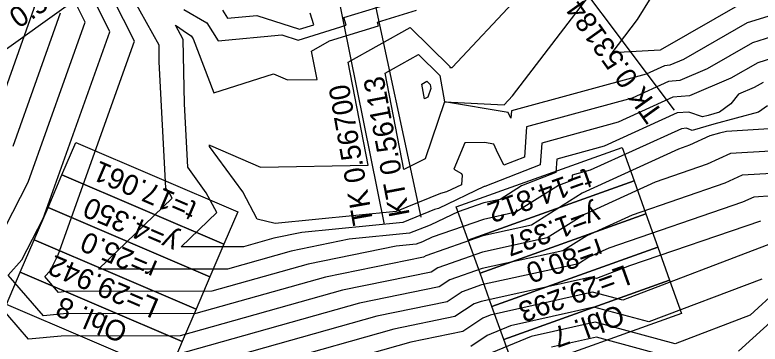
# Model space of a CAD drawing. Extents: x -549394 to -546608, y -1037055 to -1033629.
# Drawn here: x -548193 to -548066.1, y -1035675.8 to -1035619.7 of the extents above; entities that cross this region are included whole.
import ezdxf

# ---------------------------------------------------------------- set-up
doc = ezdxf.new("R2010")
doc.units = 0
for name, color, linetype in [('hlavni_vrst', 7, 'Continuous'), ('norm_vrst', 7, 'Continuous'), ('x_popis_oblouky_C11', 7, 'Continuous')]:
    doc.layers.add(name, color=color, linetype=linetype)

msp = doc.modelspace()

# ---------------------------------------------------------------- linework, layer by layer
at = {"layer": 'hlavni_vrst'}
for p, q in [((-548176.82, -1035622.58), (-548181.99, -1035612.19)), ((-548108.23, -1035633.5), (-548093.35, -1035614.04)), ((-548063.29, -1035619.52), (-548068.27, -1035621.07)), ((-548068.27, -1035621.07), (-548079.1, -1035627.29)), ((-548188.17, -1035654.39), (-548176.82, -1035622.58)), ((-548129.95, -1035629.63), (-548124.25, -1035626.43)), ((-548120.6, -1035630.04), (-548124.25, -1035626.43)), ((-548079.1, -1035627.29), (-548081.44, -1035628.29)), ((-548082.38, -1035628.37), (-548085.49, -1035629.79)), ((-548081.44, -1035628.29), (-548082.38, -1035628.37)), ((-548126.76, -1035646.05), (-548129.95, -1035629.63)), ((-548085.49, -1035629.79), (-548108.42, -1035636.05)), ((-548120.6, -1035630.04), (-548119.82, -1035634.51)), ((-548109.67, -1035635.05), (-548108.23, -1035633.5)), ((-548119.82, -1035634.51), (-548123.13, -1035644.22)), ((-548119.82, -1035634.51), (-548109.67, -1035635.05)), ((-548108.97, -1035636.34), (-548119.82, -1035634.51)), ((-548119.82, -1035634.51), (-548119.82, -1035634.51)), ((-548119.82, -1035634.51), (-548119.82, -1035634.51)), ((-548108.42, -1035636.05), (-548108.5, -1035637.32)), ((-548108.5, -1035637.32), (-548108.97, -1035636.34)), ((-548072.98, -1035639.86), (-548074.62, -1035640.33)), ((-548071.82, -1035639.55), (-548072.98, -1035639.86)), ((-548064.51, -1035639.13), (-548071.82, -1035639.55)), ((-548074.62, -1035640.33), (-548078.11, -1035641.92)), ((-548080, -1035642.57), (-548096.36, -1035650.09)), ((-548078.11, -1035641.92), (-548080, -1035642.57)), ((-548123.13, -1035644.22), (-548126.76, -1035646.05)), ((-548096.36, -1035650.09), (-548105.01, -1035655.51)), ((-548191.78, -1035661.43), (-548188.17, -1035654.39)), ((-548105.01, -1035655.51), (-548113.27, -1035657.33)), ((-548113.27, -1035657.33), (-548123.03, -1035660.72)), ((-548063.85, -1035658.55), (-548089.48, -1035668.31)), ((-548194.11, -1035664.01), (-548191.78, -1035661.43)), ((-548123.41, -1035660.97), (-548140.11, -1035664.37)), ((-548123.03, -1035660.72), (-548123.41, -1035660.97)), ((-548188.12, -1035670.96), (-548194.11, -1035664.01)), ((-548140.11, -1035664.37), (-548162.15, -1035670.57)), ((-548094.64, -1035666.91), (-548112.05, -1035670.86)), ((-548089.48, -1035668.31), (-548094.64, -1035666.91)), ((-548184.68, -1035670.62), (-548188.12, -1035670.96)), ((-548162.15, -1035670.57), (-548184.68, -1035670.62)), ((-548113.29, -1035671.36), (-548116.7, -1035673.63)), ((-548112.05, -1035670.86), (-548113.29, -1035671.36)), ((-548116.7, -1035673.63), (-548125.54, -1035675.43)), ((-548125.54, -1035675.43), (-548175.62, -1035689.53))]:
    msp.add_line(p, q, dxfattribs=at)
at = {"layer": 'norm_vrst'}
for p, q in [((-548086.94, -1035620.48), (-548081.01, -1035610.73)), ((-548181.01, -1035620.97), (-548185.45, -1035612.08)), ((-548172.62, -1035624.19), (-548178.54, -1035612.31)), ((-548118.51, -1035628.69), (-548103.93, -1035613.06)), ((-548168.44, -1035624.88), (-548172.75, -1035617.1)), ((-548136.96, -1035620.16), (-548123.43, -1035616.01)), ((-548195.87, -1035635.88), (-548189.41, -1035617.76)), ((-548069.16, -1035617.69), (-548083.11, -1035625.69)), ((-548193.3, -1035642.05), (-548185.21, -1035619.37)), ((-548164.19, -1035618.8), (-548160.3, -1035621.08)), ((-548157.65, -1035618.89), (-548156.77, -1035620.29)), ((-548142.09, -1035621.38), (-548142.69, -1035619.4)), ((-548131.24, -1035620.93), (-548124.61, -1035618.89)), ((-548190.74, -1035648.22), (-548181.01, -1035620.97)), ((-548156.77, -1035620.29), (-548151.81, -1035619.82)), ((-548151.81, -1035619.82), (-548144.54, -1035622.14)), ((-548136.56, -1035621.47), (-548136.96, -1035620.16)), ((-548131.04, -1035621.57), (-548131.24, -1035620.93)), ((-548091.28, -1035626.16), (-548086.94, -1035620.48)), ((-548165.66, -1035621.45), (-548163.6, -1035622.88)), ((-548164.31, -1035623.9), (-548165.66, -1035621.45)), ((-548160.3, -1035621.08), (-548158.37, -1035624.12)), ((-548144.73, -1035623.99), (-548136.56, -1035621.47)), ((-548144.54, -1035622.14), (-548142.09, -1035621.38)), ((-548139.42, -1035624.15), (-548131.04, -1035621.57)), ((-548136.21, -1035627.74), (-548125.68, -1035621.84)), ((-548118.93, -1035628.5), (-548125.68, -1035621.84)), ((-548060.14, -1035622.2), (-548067.37, -1035624.46)), ((-548163.6, -1035622.88), (-548162.95, -1035623.26)), ((-548162.95, -1035623.26), (-548162.62, -1035623.79)), ((-548158.37, -1035624.12), (-548147.51, -1035623.1)), ((-548147.51, -1035623.1), (-548144.73, -1035623.99)), ((-548185.6, -1035660.56), (-548172.62, -1035624.19)), ((-548164.11, -1035634.87), (-548164.31, -1035623.9)), ((-548162.62, -1035623.79), (-548159.09, -1035632.98)), ((-548142.46, -1035625.86), (-548139.42, -1035624.15)), ((-548067.37, -1035624.46), (-548075.09, -1035628.89)), ((-548168.39, -1035627.73), (-548168.44, -1035624.88)), ((-548141.52, -1035630.69), (-548142.46, -1035625.86)), ((-548083.11, -1035625.69), (-548091.28, -1035626.16)), ((-548083.11, -1035625.69), (-548083.11, -1035625.69)), ((-548083.11, -1035625.69), (-548083.11, -1035625.69)), ((-548083.11, -1035625.69), (-548083.11, -1035625.69)), ((-548083.11, -1035625.69), (-548083.11, -1035625.69)), ((-548083.11, -1035625.69), (-548083.11, -1035625.69)), ((-548056.99, -1035624.88), (-548066.47, -1035627.85)), ((-548167.28, -1035649.22), (-548168.39, -1035627.73)), ((-548132.8, -1035645.3), (-548136.21, -1035627.74)), ((-548118.93, -1035628.5), (-548118.9, -1035628.67)), ((-548066.47, -1035627.85), (-548071.08, -1035630.49)), ((-548159.09, -1035632.98), (-548148.92, -1035629.77)), ((-548148.92, -1035629.77), (-548146.58, -1035630.78)), ((-548118.9, -1035628.67), (-548118.51, -1035628.69)), ((-548075.09, -1035628.89), (-548079.77, -1035630.9)), ((-548146.58, -1035630.78), (-548141.52, -1035630.69)), ((-548123.7, -1035631.51), (-548122.83, -1035631.02)), ((-548122.27, -1035631.57), (-548122.83, -1035631.02)), ((-548081.65, -1035631.05), (-548087.88, -1035633.88)), ((-548079.77, -1035630.9), (-548081.65, -1035631.05)), ((-548071.08, -1035630.49), (-548078.1, -1035633.5)), ((-548123.21, -1035634.02), (-548123.7, -1035631.51)), ((-548122.15, -1035632.26), (-548122.65, -1035633.74)), ((-548122.27, -1035631.57), (-548122.15, -1035632.26)), ((-548067.07, -1035632.09), (-548069.73, -1035633.23)), ((-548065.57, -1035631.23), (-548067.07, -1035632.09)), ((-548078.1, -1035633.5), (-548080.92, -1035633.73)), ((-548069.73, -1035633.23), (-548071.07, -1035634.87)), ((-548163.55, -1035645.67), (-548164.11, -1035634.87)), ((-548122.65, -1035633.74), (-548123.21, -1035634.02)), ((-548087.88, -1035633.88), (-548105.84, -1035638.79)), ((-548080.92, -1035633.73), (-548090.26, -1035637.98)), ((-548071.07, -1035634.87), (-548073, -1035636.3)), ((-548064.82, -1035635.17), (-548066.33, -1035636.28)), ((-548080.19, -1035636.41), (-548092.64, -1035642.07)), ((-548078.21, -1035636.25), (-548080.19, -1035636.41)), ((-548075.87, -1035637.08), (-548078.21, -1035636.25)), ((-548074.94, -1035636.82), (-548075.87, -1035637.08)), ((-548073, -1035636.3), (-548074.94, -1035636.82)), ((-548066.33, -1035636.28), (-548073.96, -1035638.34)), ((-548090.26, -1035637.98), (-548103.26, -1035641.53)), ((-548073.96, -1035638.34), (-548077.64, -1035639.37)), ((-548105.84, -1035638.79), (-548106.19, -1035643.93)), ((-548079.46, -1035639.09), (-548095.02, -1035646.17)), ((-548078.62, -1035639.02), (-548079.46, -1035639.09)), ((-548077.64, -1035639.37), (-548078.62, -1035639.02)), ((-548159.82, -1035642.02), (-548159.83, -1035641.86)), ((-548159.83, -1035641.86), (-548159.77, -1035642)), ((-548159.82, -1035642.13), (-548159.82, -1035642.02)), ((-548154.18, -1035649.83), (-548159.82, -1035642.13)), ((-548159.77, -1035642), (-548159.67, -1035641.97)), ((-548159.67, -1035641.97), (-548151.16, -1035645.62)), ((-548116.38, -1035641.47), (-548118.22, -1035646)), ((-548113.02, -1035641.45), (-548116.38, -1035641.47)), ((-548111.44, -1035641.72), (-548113.02, -1035641.45)), ((-548110.95, -1035642.75), (-548111.44, -1035641.72)), ((-548103.26, -1035641.53), (-548103.51, -1035645.25)), ((-548092.64, -1035642.07), (-548100.68, -1035644.27)), ((-548109.74, -1035645.3), (-548110.95, -1035642.75)), ((-548071.11, -1035643.32), (-548075.09, -1035645.15)), ((-548064.3, -1035642.94), (-548071.11, -1035643.32)), ((-548106.19, -1035643.93), (-548109.74, -1035645.3)), ((-548100.68, -1035644.27), (-548100.84, -1035646.57)), ((-548160.39, -1035649.99), (-548163.55, -1035645.67)), ((-548151.16, -1035645.62), (-548132.8, -1035645.3)), ((-548118.22, -1035646), (-548116.95, -1035646.73)), ((-548103.51, -1035645.25), (-548112.98, -1035648.92)), ((-548095.02, -1035646.17), (-548098.1, -1035647.01)), ((-548075.09, -1035645.15), (-548083.94, -1035648.18)), ((-548116.95, -1035646.73), (-548116.8, -1035646.99)), ((-548116.8, -1035646.99), (-548116.93, -1035648.63)), ((-548100.84, -1035646.57), (-548106.69, -1035648.84)), ((-548098.1, -1035647.01), (-548098.16, -1035647.89)), ((-548069.13, -1035647.03), (-548072.07, -1035648.37)), ((-548064.1, -1035646.74), (-548069.13, -1035647.03)), ((-548196.57, -1035659.58), (-548190.74, -1035648.22)), ((-548116.93, -1035648.63), (-548119.5, -1035649.87)), ((-548112.98, -1035648.92), (-548113.01, -1035648.94)), ((-548106.69, -1035648.84), (-548110.34, -1035651.13)), ((-548100.4, -1035648.76), (-548107.68, -1035653.32)), ((-548098.16, -1035647.89), (-548100.4, -1035648.76)), ((-548083.94, -1035648.18), (-548095.98, -1035653.71)), ((-548072.07, -1035648.37), (-548087.89, -1035653.8)), ((-548166.59, -1035650.16), (-548167.28, -1035649.22)), ((-548166.21, -1035650.9), (-548166.59, -1035650.16)), ((-548158.62, -1035653.37), (-548160.39, -1035649.99)), ((-548151.74, -1035654.49), (-548154.18, -1035649.83)), ((-548120.48, -1035650.14), (-548128.06, -1035653.2)), ((-548113.08, -1035648.96), (-548120.82, -1035652.68)), ((-548119.5, -1035649.87), (-548120.48, -1035650.14)), ((-548113.04, -1035648.95), (-548113.08, -1035648.96)), ((-548113.01, -1035648.94), (-548113.04, -1035648.95)), ((-548178.77, -1035663.04), (-548166.21, -1035650.9)), ((-548110.34, -1035651.13), (-548113.12, -1035651.74)), ((-548067.15, -1035650.73), (-548069.05, -1035651.6)), ((-548063.89, -1035650.54), (-548067.15, -1035650.73)), ((-548120.82, -1035652.68), (-548121.52, -1035652.87)), ((-548113.12, -1035651.74), (-548117.5, -1035653.27)), ((-548069.05, -1035651.6), (-548091.84, -1035659.41)), ((-548164.67, -1035659.22), (-548158.62, -1035653.37)), ((-548128.06, -1035653.2), (-548148.65, -1035655.24)), ((-548121.52, -1035652.87), (-548126.92, -1035655.06)), ((-548117.5, -1035653.27), (-548122.13, -1035655.49)), ((-548107.68, -1035653.32), (-548113.19, -1035654.54)), ((-548095.98, -1035653.71), (-548102.34, -1035657.7)), ((-548087.89, -1035653.8), (-548095.6, -1035657.34)), ((-548148.65, -1035655.24), (-548151.74, -1035654.49)), ((-548126.92, -1035655.06), (-548144.1, -1035656.76)), ((-548113.19, -1035654.54), (-548121.92, -1035657.57)), ((-548066.03, -1035654.82), (-548088.34, -1035662.47)), ((-548122.55, -1035655.61), (-548125.79, -1035656.91)), ((-548122.13, -1035655.49), (-548122.55, -1035655.61)), ((-548148.86, -1035657.73), (-548154.07, -1035659.2)), ((-548144.1, -1035656.76), (-548148.86, -1035657.73)), ((-548125.79, -1035656.91), (-548136.06, -1035657.93)), ((-548121.92, -1035657.57), (-548123.45, -1035658.3)), ((-548102.34, -1035657.7), (-548113.35, -1035660.12)), ((-548095.6, -1035657.34), (-548099.67, -1035659.89)), ((-548136.06, -1035657.93), (-548145.94, -1035659.94)), ((-548124.65, -1035658.77), (-548128.03, -1035659.11)), ((-548123.58, -1035658.34), (-548124.65, -1035658.77)), ((-548123.45, -1035658.3), (-548123.58, -1035658.34)), ((-548154.07, -1035659.2), (-548164.67, -1035659.22)), ((-548145.94, -1035659.94), (-548156.77, -1035662.99)), ((-548128.03, -1035659.11), (-548143.03, -1035662.15)), ((-548113.35, -1035660.12), (-548120.97, -1035662.77)), ((-548099.67, -1035659.89), (-548113.42, -1035662.92)), ((-548091.84, -1035659.41), (-548095.22, -1035660.96)), ((-548187, -1035663.28), (-548185.6, -1035660.56)), ((-548095.22, -1035660.96), (-548097, -1035662.08)), ((-548143.03, -1035662.15), (-548159.46, -1035666.78)), ((-548120.97, -1035662.77), (-548122.07, -1035663.5)), ((-548097, -1035662.08), (-548113.5, -1035665.71)), ((-548088.34, -1035662.47), (-548093.94, -1035664.6)), ((-548058.19, -1035662.03), (-548067.77, -1035670.85)), ((-548190.65, -1035674.96), (-548200.33, -1035663.74)), ((-548187.9, -1035664.28), (-548187, -1035663.28)), ((-548156.77, -1035662.99), (-548178.77, -1035663.04)), ((-548122.07, -1035663.5), (-548137.2, -1035666.58)), ((-548113.42, -1035662.92), (-548118.9, -1035664.82)), ((-548185.58, -1035666.97), (-548187.9, -1035664.28)), ((-548118.9, -1035664.82), (-548120.72, -1035666.04)), ((-548094.87, -1035664.35), (-548100.26, -1035665.58)), ((-548093.94, -1035664.6), (-548094.87, -1035664.35)), ((-548065.81, -1035664.7), (-548085.01, -1035672.01)), ((-548137.2, -1035666.58), (-548164.85, -1035674.36)), ((-548120.72, -1035666.04), (-548134.28, -1035668.79)), ((-548113.5, -1035665.71), (-548116.83, -1035666.87)), ((-548100.26, -1035665.58), (-548113.58, -1035668.5)), ((-548184.25, -1035666.84), (-548185.58, -1035666.97)), ((-548159.46, -1035666.78), (-548184.25, -1035666.84)), ((-548116.83, -1035666.87), (-548119.38, -1035668.57)), ((-548134.28, -1035668.79), (-548167.54, -1035678.16)), ((-548119.38, -1035668.57), (-548131.37, -1035671)), ((-548114.76, -1035668.91), (-548118.04, -1035671.1)), ((-548113.58, -1035668.5), (-548114.76, -1035668.91)), ((-548094.42, -1035669.47), (-548108.56, -1035672.68)), ((-548085.01, -1035672.01), (-548094.42, -1035669.47)), ((-548131.37, -1035671), (-548170.23, -1035681.95)), ((-548118.04, -1035671.1), (-548128.45, -1035673.22)), ((-548067.77, -1035670.85), (-548080.55, -1035675.72)), ((-548063.08, -1035670.88), (-548069.73, -1035677)), ((-548108.56, -1035672.68), (-548112.56, -1035674.3)), ((-548094.19, -1035672.03), (-548105.08, -1035674.5)), ((-548080.55, -1035675.72), (-548094.19, -1035672.03)), ((-548128.45, -1035673.22), (-548172.93, -1035685.74)), ((-548112.56, -1035674.3), (-548115.36, -1035676.17)), ((-548185.11, -1035674.41), (-548190.65, -1035674.96)), ((-548164.85, -1035674.36), (-548185.11, -1035674.41)), ((-548105.08, -1035674.5), (-548111.82, -1035677.24)), ((-548093.96, -1035674.58), (-548101.59, -1035676.31)), ((-548076.09, -1035679.42), (-548093.96, -1035674.58))]:
    msp.add_line(p, q, dxfattribs=at)
at = {"layer": 'x_popis_oblouky_C11'}
for points in [[(-548105.53, -1035602.82), (-548080.7, -1035635.92)], [(-548164.27, -1035603.91), (-548197.9, -1035628.01)], [(-548132.55, -1035613.7), (-548123.86, -1035654.15)], [(-548138.3, -1035614.86), (-548130.1, -1035655.41)]]:
    msp.add_lwpolyline(points, dxfattribs=at)
for points in [[(-548157.4, -1035658.78), (-548184.97, -1035646.97), (-548182.61, -1035641.46), (-548155.03, -1035653.27)], [(-548087.55, -1035647.95), (-548115.79, -1035658.07), (-548117.81, -1035652.42), (-548089.57, -1035642.31)], [(-548159.76, -1035664.3), (-548187.34, -1035652.49), (-548184.97, -1035646.97), (-548157.4, -1035658.78)], [(-548085.53, -1035653.6), (-548113.77, -1035663.72), (-548115.79, -1035658.07), (-548087.55, -1035647.95)], [(-548162.12, -1035669.81), (-548189.7, -1035658), (-548187.34, -1035652.49), (-548159.76, -1035664.3)], [(-548083.5, -1035659.25), (-548111.75, -1035669.36), (-548113.77, -1035663.72), (-548085.53, -1035653.6)], [(-548164.48, -1035675.33), (-548192.06, -1035663.52), (-548189.7, -1035658), (-548162.12, -1035669.81)], [(-548081.48, -1035664.9), (-548109.73, -1035675.01), (-548111.75, -1035669.36), (-548083.5, -1035659.25)], [(-548166.84, -1035680.84), (-548194.42, -1035669.03), (-548192.06, -1035663.52), (-548164.48, -1035675.33)], [(-548079.46, -1035670.55), (-548107.7, -1035680.66), (-548109.73, -1035675.01), (-548081.48, -1035664.9)]]:
    msp.add_lwpolyline(points, close=True, dxfattribs=at)

# ---------------------------------------------------------------- texts
for s, rotation, p in [('KT 0.59695', 34.2579, (-548198.38, -1035626.22)), ('TK 0.53184', 125.5009, (-548082.46, -1035636.47)), ('KT 0.56113', 100.7433, (-548125.73, -1035653.73)), ('TK 0.56700', 100.06, (-548131.92, -1035655.16)), ('t=17.061', 156.8394, (-548161.75, -1035651.7)), ('t=14.812', 199.7205, (-548095.56, -1035645.73)), ('y=4.350', 156.8394, (-548164.89, -1035657.27)), ('y=1.337', 199.7205, (-548094.07, -1035651.95)), ('r=25.0', 156.8394, (-548168.47, -1035661.78)), ('r=80.0', 199.7205, (-548093.63, -1035657.69)), ('L=29.942', 156.8394, (-548168.2, -1035668.24)), ('L=29.293', 199.7205, (-548089.03, -1035662.23)), ('Obl. 8', 156.8394, (-548173.51, -1035672.49)), ('Obl. 7', 199.7205, (-548090.02, -1035668.96))]:
    msp.add_text(s, height=3.5, rotation=rotation, dxfattribs=at).set_placement(p)

doc.saveas('drawing.dxf')
